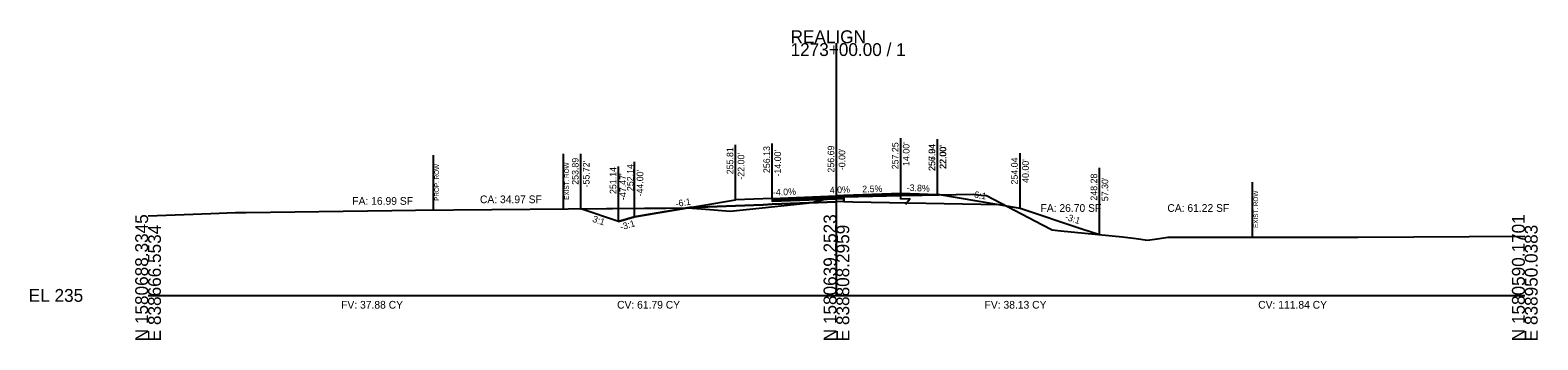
# Model space of a CAD drawing. Extents: x -26 to 6303, y -16 to 9563.
# Drawn here: x 4974.3 to 5302.8, y 6490.3 to 6557.8 of the extents above; entities that cross this region are included whole.
import ezdxf

# ---------------------------------------------------------------- set-up
doc = ezdxf.new("R2010")
doc.units = 0
for name, color, linetype in [('ASPHALT_19MM1', 7, 'Continuous'), ('ASPHALT_9_5MM1', 7, 'Continuous'), ('CONST_DCH', 7, 'Continuous'), ('CONST_LV3', 7, 'Continuous'), ('Default', 7, 'Continuous'), ('Draft_XS_Grid', 7, 'Continuous'), ('DTM_TEMP_DROP', 7, 'Continuous'), ('DTM_X_GROUND', 7, 'Continuous'), ('X_TRANS_EOP', 7, 'Continuous'), ('XS_CELL', 7, 'Continuous'), ('XS_M_SHAPES_EARTHWORK', 7, 'Continuous'), ('XS_P_ASPHALT', 7, 'Continuous'), ('XS_P_GROUND', 7, 'Continuous'), ('XS_P_ROW', 7, 'Continuous'), ('XS_P_SHOULDER', 7, 'Continuous'), ('XS_P_SUBGRADE_GRANULAR', 7, 'Continuous'), ('XS_P_SUBGRADE_LEVELING', 7, 'Continuous'), ('XS_P_SUBGRADE_MILLING', 7, 'Continuous'), ('XS_P_TX_CLEARZONE', 7, 'Continuous'), ('XS_P_TX_FS_BS', 7, 'Continuous'), ('XS_SHEET_EW_TX_AREA', 7, 'Continuous'), ('XS_SHEET_EW_TX_VOLUME', 7, 'Continuous'), ('XS_X_ROW', 7, 'Continuous')]:
    doc.layers.add(name, color=color, linetype=linetype)

msp = doc.modelspace()

# ---------------------------------------------------------------- linework, layer by layer
at = {"layer": 'ASPHALT_19MM1'}
msp.add_lwpolyline([(5136, 6520.8), (5136, 6520.53), (5150, 6521.09), (5150, 6521.09), (5150, 6521.09), (5151.6, 6521.15), (5151.6, 6521.15), (5151.6, 6521.42), (5150, 6521.36), (5150, 6521.36), (5150, 6521.36), (5136, 6520.8), (5136, 6520.8)], dxfattribs=at)
at = {"layer": 'ASPHALT_9_5MM1'}
msp.add_lwpolyline([(5136, 6521.13), (5150, 6521.69), (5150, 6521.69), (5150, 6521.69), (5151.6, 6521.75), (5151.6, 6521.63), (5150, 6521.57), (5150, 6521.57), (5150, 6521.57), (5136, 6521.01), (5136, 6521.13)], dxfattribs=at)
at = {"layer": 'CONST_LV3'}
for points in [[(5151.6, 6521.75), (5150, 6521.69), (5150, 6521.69)], [(5172, 6521.94), (5151.6, 6521.75), (5151.6, 6521.75)]]:
    msp.add_lwpolyline(points, dxfattribs=at)
at = {"layer": 'Default'}
msp.add_lwpolyline([(5136, 6521.01), (5136, 6520.8), (5150, 6521.36), (5150, 6521.36), (5150, 6521.36), (5151.6, 6521.42), (5151.6, 6521.42), (5151.6, 6521.63), (5150, 6521.57), (5150, 6521.57), (5150, 6521.57), (5136, 6521.01), (5136, 6521.01)], dxfattribs=at)
at = {"layer": 'DTM_X_GROUND'}
msp.add_lwpolyline([(5000, 6517.38), (5007.87, 6517.63), (5013.65, 6517.85), (5019.08, 6518.05), (5021.4, 6518.08), (5053.15, 6518.52), (5058.28, 6518.58), (5108.19, 6519), (5111.2, 6519.01), (5112.86, 6519.03), (5117.86, 6519.07), (5118.58, 6519.01), (5120.57, 6518.85), (5126.86, 6518.36), (5133.14, 6519.02), (5135.22, 6519.23), (5143.5, 6520.13), (5144.74, 6520.26), (5145.22, 6520.39), (5147.98, 6521.12), (5150.88, 6521.44), (5151.6, 6521.51), (5154.72, 6521.58), (5165.68, 6521.83), (5168.65, 6521.89), (5179.8, 6522.08), (5181.57, 6521.89), (5182.67, 6521.78), (5194.89, 6515.38), (5197.01, 6514.27), (5198.91, 6514.08), (5212.37, 6512.79), (5215.31, 6512.38), (5217.76, 6512.02), (5219.88, 6512.36), (5222.27, 6512.73), (5230.94, 6512.72), (5240.34, 6512.71), (5245.59, 6512.7), (5263.69, 6512.71), (5300, 6512.95)], dxfattribs=at)
at = {"layer": 'XS_CELL'}
for p, q in [((5150, 6500), (5150, 6555)), ((5000, 6500), (5150, 6500)), ((5150, 6500), (5300, 6500))]:
    msp.add_line(p, q, dxfattribs=at)
at = {"layer": 'XS_M_SHAPES_EARTHWORK'}
for points in [[(5143.95, 6520.18), (5144.74, 6520.26), (5145.22, 6520.39), (5147.98, 6521.12), (5150.88, 6521.44), (5151.6, 6521.51), (5151.6, 6521.42), (5151.6, 6521.15), (5151.6, 6520.48), (5150, 6520.42)], [(5164, 6521.8), (5165.68, 6521.83), (5168.65, 6521.89), (5171.99, 6521.94), (5164, 6522.25), (5164, 6522.13)], [(5094.28, 6518.89), (5108.19, 6519), (5111.2, 6519.01), (5112.86, 6519.03), (5117.56, 6519.07), (5106, 6517.14), (5102.53, 6516.14)], [(5117.56, 6519.07), (5117.86, 6519.07), (5118.58, 6519.01), (5120.57, 6518.85), (5126.86, 6518.36), (5133.14, 6519.02), (5135.22, 6519.23), (5143.5, 6520.13), (5143.95, 6520.18), (5136, 6519.86), (5134, 6519.78), (5117.97, 6519.14)]]:
    msp.add_lwpolyline(points, close=True, dxfattribs=at)
at = {"layer": 'XS_P_ASPHALT'}
msp.add_lwpolyline([(5151.6, 6521.75), (5151.6, 6521.63), (5164, 6522.13), (5164, 6522.25), (5151.6, 6521.75)], dxfattribs=at)
at = {"layer": 'XS_P_GROUND'}
for points in [[(5172, 6522.04), (5190, 6519.04), (5203.5, 6514.54), (5207.3, 6513.28)], [(5172, 6521.94), (5172, 6521.94)], [(5102.53, 6516.14), (5094.28, 6518.89)], [(5102.53, 6516.14), (5102.53, 6516.14), (5106, 6517.14), (5128, 6520.81), (5128, 6520.81)]]:
    msp.add_lwpolyline(points, dxfattribs=at)
at = {"layer": 'XS_P_ROW'}
msp.add_line((5062.19, 6518.61), (5062.19, 6530.61), dxfattribs=at)
at = {"layer": 'XS_P_SHOULDER'}
for points in [[(5172, 6521.94), (5164, 6522.25), (5164, 6522.25)], [(5136, 6521.13), (5128, 6520.81)]]:
    msp.add_lwpolyline(points, dxfattribs=at)
at = {"layer": 'XS_P_SUBGRADE_GRANULAR'}
for points in [[(5151.6, 6520.48), (5151.6, 6521.75)], [(5164, 6520.98), (5164, 6522.13)], [(5117.97, 6519.14), (5134, 6519.78), (5134, 6519.78), (5136, 6519.86), (5136, 6519.86)], [(5136, 6519.86), (5150, 6520.42), (5150, 6520.42)], [(5151.6, 6520.48), (5150, 6520.42), (5150, 6520.42)], [(5151.6, 6520.48), (5153.6, 6520.44), (5185.43, 6519.81)], [(5165.07, 6519.87), (5166, 6521.06), (5166, 6521.06), (5166, 6521.06), (5164, 6520.98)]]:
    msp.add_lwpolyline(points, dxfattribs=at)
at = {"layer": 'XS_P_SUBGRADE_LEVELING'}
msp.add_lwpolyline([(5154.72, 6521.75), (5151.6, 6521.63), (5151.6, 6521.63), (5151.6, 6521.51), (5151.6, 6521.51), (5154.72, 6521.58), (5154.72, 6521.58), (5164, 6521.8), (5164, 6522.13), (5154.72, 6521.75), (5154.72, 6521.75)], dxfattribs=at)
at = {"layer": 'XS_P_SUBGRADE_MILLING'}
for points in [[(5164, 6521.8), (5154.72, 6521.58), (5154.72, 6521.58), (5151.6, 6521.51), (5151.6, 6521.51)], [(5151.6, 6521.51), (5151.6, 6521.51), (5154.72, 6521.58), (5154.72, 6521.58), (5164, 6521.8)]]:
    msp.add_lwpolyline(points, dxfattribs=at)
at = {"layer": 'XS_P_TX_CLEARZONE'}
for p, q in [((5128, 6520.81), (5128, 6532.81)), ((5136, 6521.13), (5136, 6533.13)), ((5150, 6521.69), (5150, 6533.69)), ((5164, 6522.25), (5164, 6534.25)), ((5172, 6522.04), (5172, 6534.04)), ((5172, 6521.94), (5172, 6533.94)), ((5094.28, 6518.89), (5094.28, 6530.89)), ((5102.53, 6516.14), (5102.53, 6528.14)), ((5106, 6517.14), (5106, 6529.14)), ((5190, 6519.04), (5190, 6531.04)), ((5207.3, 6513.28), (5207.3, 6527.82))]:
    msp.add_line(p, q, dxfattribs=at)
at = {"layer": 'XS_X_ROW'}
for p, q in [((5090.51, 6518.85), (5090.51, 6530.85)), ((5240.68, 6512.71), (5240.68, 6524.71))]:
    msp.add_line(p, q, dxfattribs=at)

# ---------------------------------------------------------------- texts
at = {"layer": 'CONST_DCH'}
for p in [(5171.92, 6521.92), (5189.92, 6518.92)]:
    msp.add_text('X', height=0.24, dxfattribs=at).set_placement(p)
at = {"layer": 'Draft_XS_Grid'}
msp.add_text('-', height=0.0001, dxfattribs=at).set_placement((5000, 6500))
at = {"layer": 'DTM_TEMP_DROP'}
for p in [(5149.92, 6521.57), (5151.52, 6521.63), (5163.92, 6522.13), (5135.92, 6521.01)]:
    msp.add_text('X', height=0.24, dxfattribs=at).set_placement(p)
at = {"layer": 'X_TRANS_EOP'}
for p in [(5171.92, 6521.82), (5094.2, 6518.77)]:
    msp.add_text('X', height=0.24, dxfattribs=at).set_placement(p)
at = {"layer": 'XS_CELL'}
for s, p in [('REALIGN', (5140, 6555)), ('1273+00.00 / 1', (5140, 6552.2)), ('EL 235', (4974, 6498.6))]:
    msp.add_text(s, height=2.8, dxfattribs=at).set_placement(p)
for s, p in [('N 1580688.3345', (5000, 6490)), ('E 838666.5534', (5002.8, 6490)), ('N 1580639.2523', (5150, 6490)), ('E 838808.2959', (5152.8, 6490)), ('N 1580590.1701', (5300, 6490)), ('E 838950.0383', (5302.8, 6490))]:
    msp.add_text(s, height=2.8, rotation=90, dxfattribs=at).set_placement(p)
at = {"layer": 'XS_P_ASPHALT'}
msp.add_text('X', height=0.24, dxfattribs=at).set_placement((5105.92, 6517.02))
at = {"layer": 'XS_P_GROUND'}
msp.add_text('X', height=0.24, dxfattribs=at).set_placement((5171.92, 6521.82))
at = {"layer": 'XS_P_ROW'}
msp.add_text('PROP. ROW', height=1, rotation=90, dxfattribs=at).set_placement((5063.39, 6520.61))
at = {"layer": 'XS_P_SHOULDER'}
for p in [(5171.92, 6521.82), (5127.92, 6520.69), (5207.22, 6513.16)]:
    msp.add_text('X', height=0.24, dxfattribs=at).set_placement(p)
at = {"layer": 'XS_P_SUBGRADE_GRANULAR'}
for p in [(5171.92, 6521.82), (5102.45, 6516.02), (5207.22, 6513.16)]:
    msp.add_text('X', height=0.24, dxfattribs=at).set_placement(p)
at = {"layer": 'XS_P_TX_CLEARZONE'}
for s, p in [('255.81', (5127.52, 6526.42)), ('256.13', (5135.52, 6526.67)), ("-14.00'", (5137.92, 6525.92)), ('256.69', (5149.52, 6526.79)), ("-0.00'", (5151.92, 6527.3)), ('257.25', (5163.52, 6527.5)), ("14.00'", (5165.92, 6528.22)), ('257.04', (5171.52, 6527.18)), ('256.94', (5171.52, 6527.12)), ("22.00'", (5173.92, 6527.65)), ("22.00'", (5173.92, 6527.55)), ('253.89', (5093.8, 6524.12)), ("-55.72'", (5096.2, 6523.54)), ('252.14', (5105.79, 6522.75)), ("-22.00'", (5129.92, 6525.24)), ('254.04', (5189.52, 6524.18)), ("40.00'", (5191.92, 6524.54)), ('251.14', (5102.05, 6522.11)), ("-47.47'", (5104.16, 6520.79)), ("-44.00'", (5107.92, 6521.57)), ('248.28', (5206.82, 6520.67)), ("57.30'", (5209.22, 6520.54))]:
    msp.add_text(s, height=1.44, rotation=90, dxfattribs=at).set_placement(p)
at = {"layer": 'XS_P_TX_FS_BS'}
for s, rotation, p in [('-4.0%', 2.2906, (5136.18, 6521.74)), ('4.0%', 2.2906, (5148.57, 6522.23)), ('2.5%', 1.4384, (5155.64, 6522.46)), ('-3.8%', 357.8097, (5165.29, 6522.8)), ('-6:1', 350.5377, (5179.28, 6521.44)), ('-6:1', 9.4642, (5115.08, 6519.26)), ('3:1', 341.5651, (5096.72, 6516.09)), ('-3:1', 16.1889, (5103.07, 6514.18)), ('-3:1', 341.5651, (5199.71, 6516.55))]:
    msp.add_text(s, height=1.44, rotation=rotation, dxfattribs=at).set_placement(p)
at = {"layer": 'XS_SHEET_EW_TX_AREA'}
for s, p in [('FA: 16.99 SF', (5044.5, 6519.76)), ('CA: 34.97 SF', (5072.32, 6520.11)), ('FA: 26.70 SF', (5194.47, 6518.22)), ('CA: 61.22 SF', (5222.11, 6518.22))]:
    msp.add_text(s, height=1.68, dxfattribs=at).set_placement(p)
at = {"layer": 'XS_SHEET_EW_TX_VOLUME'}
for s, p in [('FV: 37.88 CY', (5042.07, 6497.12)), ('CV: 61.79 CY', (5102.2, 6497.12)), ('FV: 38.13 CY', (5182.28, 6497.12)), ('CV: 111.84 CY', (5241.91, 6497.12))]:
    msp.add_text(s, height=1.68, dxfattribs=at).set_placement(p)
at = {"layer": 'XS_X_ROW'}
for p in [(5091.71, 6520.85), (5241.88, 6514.71)]:
    msp.add_text('EXIST. ROW', height=1, rotation=90, dxfattribs=at).set_placement(p)

doc.saveas('drawing.dxf')
